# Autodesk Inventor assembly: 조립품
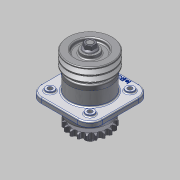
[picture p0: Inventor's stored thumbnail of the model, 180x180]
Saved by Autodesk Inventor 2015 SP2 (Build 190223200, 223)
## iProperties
Created: 2015-07
Part Number: 조립품
Document SubType Name: Assembly
Designer: AMC
Author: AMC
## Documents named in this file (12)
- C:\Users\AMC\Desktop\450735V1004\조립품.iam
- C:\Users\AMC\Desktop\450735V1004\본체.ipt
- C:\Users\AMC\Desktop\450735V1004\2-커버.ipt
- C:\Users\AMC\Desktop\450735V1004\3-축.ipt
- C:\Users\AMC\Desktop\450735V1004\4-V벨트풀리.ipt
- C:\Users\AMC\Desktop\450735V1004\5-체인 스프로킷.ipt
- C:\Users\AMC\Desktop\450735V1004\6-베어링 6206.ipt
- C:\Users\AMC\Desktop\450735V1004\7-부시.ipt
- C:\Users\AMC\Desktop\450735V1004\8-오일실 30x42.ipt
- C:\Users\AMC\Desktop\450735V1004\9-M16-너트.ipt
- C:\Users\AMC\Desktop\450735V1004\10-M6.ipt
- C:\Users\AMC\Desktop\450735V1004\11-키 6x6.ipt
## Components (22 placed, 10 different names)
1. 2-커버:1
2. 3-축:1
3. 4-V벨트풀리:1 — 각도:1
4. 5-체인 스프로킷:1 — 각도:2
5. 6-베어링 6206:1
6. 7-부시:1
7. 8-8-오일실 30x42:1
8. 9-M16 너트:1
9. 10-M6:1
10. 11-키 6x6:1 — 각도:1
11. 6-베어링 6206:2
12. 2-커버:2
13. 10-M6:2
14. 10-M6:3
15. 10-M6:4
16. 10-M6:6
17. 10-M6:7
18. 10-M6:8
19. 10-M6:9
20. 8-8-오일실 30x42:2
21. 11-키 6x6:2 — 각도:2
22. 9-M16 너트:2
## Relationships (2: Angle 2)
- 각도:1 [Angle]: 4-V벨트풀리:1 ↔ 11-키 6x6:1
- 각도:2 [Angle]: 5-체인 스프로킷:1 ↔ 11-키 6x6:2
